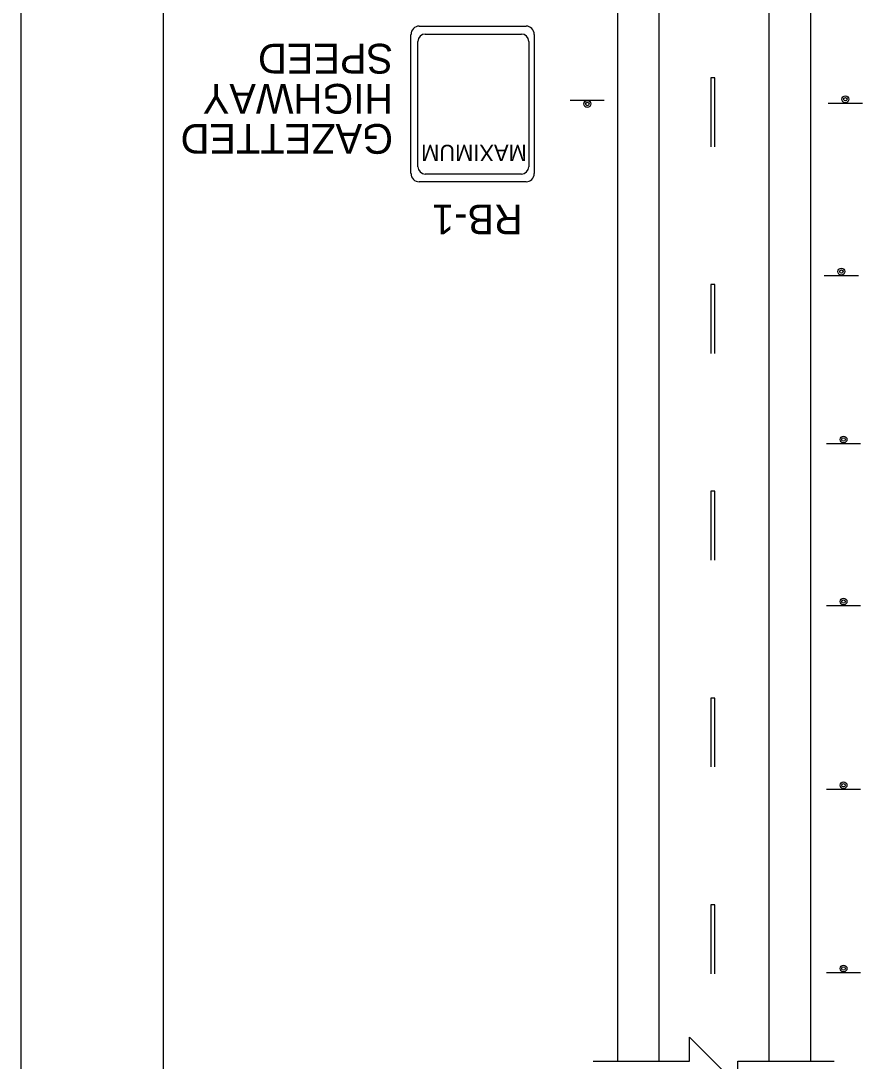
# Model space of a CAD drawing. Extents: x 2179 to 2395, y 134 to 413.
# Drawn here: x 2178.7 to 2238.7, y 178.2 to 251.3 of the extents above; entities that cross this region are included whole.
import ezdxf

# ---------------------------------------------------------------- set-up
doc = ezdxf.new("R2010")
doc.units = 0
for name, color, linetype in [('Level 10', 7, 'Continuous'), ('Level 2', 7, 'Continuous'), ('Level 20', 7, 'Continuous'), ('Level 44', 7, 'Continuous'), ('Level 5', 7, 'Continuous'), ('Level 60', 7, 'Continuous')]:
    doc.layers.add(name, color=color, linetype=linetype)

# ---------------------------------------------------------------- blocks, each defined once
blk = doc.blocks.new('BREAK')
at = {"layer": 'Level 20'}
blk.add_lwpolyline([(-12.499, 0), (-2.5, 0), (-2.5, 2.5), (0, 0), (2.501, -2.501), (2.501, 0), (12.501, 0)], dxfattribs=at)
blk = doc.blocks.new('BR')
at = {"layer": 'Level 20', "xscale": 0.4837996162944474, "yscale": 0.4837996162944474}
blk.add_blockref('BREAK', (1.209, 0), dxfattribs=at)

msp = doc.modelspace()

# ---------------------------------------------------------------- linework, layer by layer
at = {"layer": 'Level 10'}
for p, q in [((2234.191, 178.244), (2234.191, 326.608)), ((2220.644, 178.244), (2220.644, 313.635)), ((2231.288, 178.244), (2231.288, 293.208)), ((2223.547, 178.244), (2223.547, 288.758))]:
    msp.add_line(p, q, dxfattribs=at)
at = {"layer": 'Level 2'}
for p, q in [((2227.172, 247.28), (2227.172, 242.442)), ((2227.462, 247.28), (2227.172, 247.28)), ((2227.462, 242.442), (2227.462, 247.28)), ((2227.172, 232.766), (2227.172, 227.928)), ((2227.462, 232.766), (2227.172, 232.766)), ((2227.462, 227.928), (2227.462, 232.766)), ((2227.172, 218.252), (2227.172, 213.414)), ((2227.462, 218.252), (2227.172, 218.252)), ((2227.462, 213.414), (2227.462, 218.252)), ((2227.172, 203.738), (2227.172, 198.9)), ((2227.462, 203.738), (2227.172, 203.738)), ((2227.462, 198.9), (2227.462, 203.738)), ((2227.172, 189.224), (2227.172, 184.386)), ((2227.462, 189.224), (2227.172, 189.224)), ((2227.462, 184.386), (2227.462, 189.224))]:
    msp.add_line(p, q, dxfattribs=at)
at = {"layer": 'Level 44'}
for p, q in [((2206.715, 250.915), (2214.211, 250.915)), ((2206.136, 240.563), (2206.136, 250.333)), ((2206.616, 241.044), (2206.616, 249.839)), ((2207.137, 250.36), (2213.883, 250.36)), ((2214.403, 249.841), (2214.403, 249.839)), ((2214.403, 249.839), (2214.403, 241.044)), ((2214.789, 250.337), (2214.789, 250.333)), ((2214.789, 250.333), (2214.789, 240.563)), ((2217.309, 245.716), (2219.705, 245.716)), ((2235.421, 245.509), (2237.818, 245.509)), ((2213.883, 240.524), (2207.137, 240.524)), ((2214.211, 239.984), (2206.715, 239.984)), ((2235.143, 233.41), (2237.54, 233.41)), ((2235.294, 221.621), (2237.69, 221.621)), ((2235.294, 210.242), (2237.69, 210.242)), ((2235.294, 197.347), (2237.69, 197.347)), ((2235.294, 184.479), (2237.69, 184.479))]:
    msp.add_line(p, q, dxfattribs=at)
for centre, radius in [((2218.512, 245.447), 0.24), ((2218.512, 245.447), 0.12), ((2236.625, 245.778), 0.24), ((2236.625, 245.778), 0.12), ((2236.347, 233.679), 0.24), ((2236.347, 233.679), 0.12), ((2236.497, 221.889), 0.24), ((2236.497, 221.889), 0.12), ((2236.497, 210.511), 0.24), ((2236.497, 210.511), 0.12), ((2236.497, 197.616), 0.24), ((2236.497, 197.616), 0.12), ((2236.497, 184.747), 0.24), ((2236.497, 184.747), 0.12)]:
    msp.add_circle(centre, radius, dxfattribs=at)
for centre, radius, start, end in [((2206.715, 250.335), 0.578, 90, 179.99999), ((2214.21, 250.335), 0.578, 360, 89.99999), ((2207.137, 249.841), 0.52, 90, 179.99999), ((2213.883, 249.841), 0.52, 360, 89.99999), ((2206.715, 240.563), 0.578, 179.99999, 269.99999), ((2207.137, 241.046), 0.52, 179.99999, 269.99999), ((2213.883, 241.046), 0.52, 270, 359.99999), ((2214.21, 240.563), 0.578, 270, 359.99999)]:
    msp.add_arc(centre, radius, start, end, dxfattribs=at)
at = {"layer": 'Level 60'}
for points in [[(2394.748, 412.757), (2178.748, 412.757), (2178.748, 133.757), (2394.748, 133.757)], [(2375.622, 401.948), (2188.748, 401.948), (2188.748, 144.566), (2375.622, 144.566)]]:
    msp.add_lwpolyline(points, close=True, dxfattribs=at)

# ---------------------------------------------------------------- block references
at = {"layer": 'Level 20', "xscale": 1.4, "yscale": 1.4}
msp.add_blockref('BR', (2225.687, 178.244), dxfattribs=at)

# ---------------------------------------------------------------- texts
at = {"layer": 'Level 10'}
msp.add_text('RB-1', height=2.09, rotation=180, dxfattribs=at).set_placement((2213.98, 238.385))
at = {"layer": 'Level 44'}
msp.add_text('MAXIMUM', height=1.1467, rotation=180, dxfattribs=at).set_placement((2214.262, 242.583))
at = {"layer": 'Level 5'}
for s, p in [('SPEED', (2204.876, 249.674)), ('HIGHWAY', (2204.876, 246.859)), ('GAZETTED', (2204.876, 244.043))]:
    msp.add_text(s, height=2.09, rotation=180, dxfattribs=at).set_placement(p)

doc.saveas('drawing.dxf')
